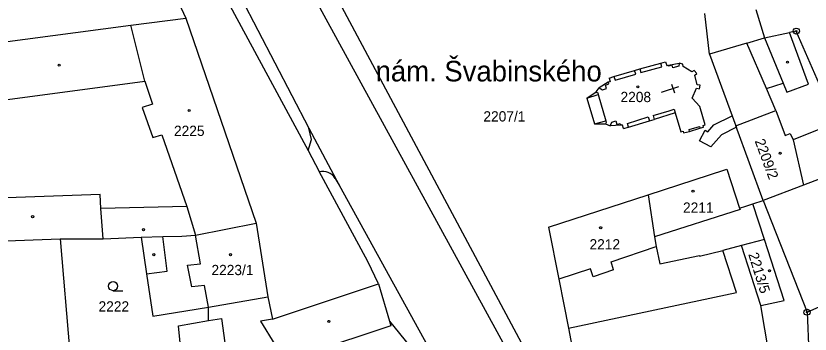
# Model space of a CAD drawing. Extents: x -755819 to -753140, y -1169796 to -1166000.
# Drawn here: x -754828 to -754696.6, y -1168215.6 to -1168163 of the extents above; entities that cross this region are included whole.
import ezdxf

# ---------------------------------------------------------------- set-up
doc = ezdxf.new("R2010")
doc.units = 0
for name, color, linetype in [('Vrstva 1', 7, 'Continuous'), ('Vrstva 15', 7, 'Continuous'), ('Vrstva 18', 7, 'Continuous'), ('Vrstva 19', 7, 'Continuous'), ('Vrstva 24', 7, 'Continuous'), ('Vrstva 25', 7, 'Continuous'), ('Vrstva 27', 7, 'Continuous'), ('Vrstva 4', 7, 'Continuous')]:
    doc.layers.add(name, color=color, linetype=linetype)

msp = doc.modelspace()

# ---------------------------------------------------------------- linework, layer by layer
at = {"layer": 'Vrstva 1'}
for p, q in [((-754811.6, -1168137.91), (-754799.93, -1168163.35)), ((-754801.63, -1168138.99), (-754779.58, -1168181.56)), ((-754787.61, -1168143.57), (-754722.5, -1168262.7)), ((-754801.06, -1168145.63), (-754779.7, -1168185.27)), ((-754731.38, -1168241.34), (-754774.47, -1168160.79)), ((-754713.27, -1168169.33), (-754714.08, -1168162.61)), ((-754809.01, -1168164.54), (-754799.93, -1168163.35)), ((-754799.93, -1168163.35), (-754788.28, -1168197.26)), ((-754834.8, -1168167.91), (-754809.01, -1168164.54)), ((-754698.93, -1168165.5), (-754700.07, -1168165.74)), ((-754692.48, -1168180.38), (-754698.93, -1168165.5)), ((-754707.1, -1168167.47), (-754704.17, -1168166.59)), ((-754704.17, -1168166.59), (-754700.07, -1168165.74)), ((-754707.1, -1168167.47), (-754713.27, -1168169.33)), ((-754713.27, -1168169.33), (-754708.92, -1168181.18)), ((-754724.84, -1168171.76), (-754721.32, -1168170.79)), ((-754721.32, -1168170.79), (-754720.55, -1168170.57)), ((-754720.55, -1168170.57), (-754720.37, -1168171.17)), ((-754720.07, -1168171.14), (-754718.28, -1168170.82)), ((-754717.69, -1168170.97), (-754718.28, -1168170.82)), ((-754717.67, -1168171.33), (-754717.69, -1168170.97)), ((-754729.09, -1168173.02), (-754725.68, -1168172.03)), ((-754725.68, -1168172.03), (-754724.84, -1168171.76)), ((-754720.37, -1168171.17), (-754720.07, -1168171.14)), ((-754716.23, -1168172.26), (-754717.67, -1168171.33)), ((-754715.85, -1168172.03), (-754716.23, -1168172.26)), ((-754715.39, -1168172.49), (-754715.85, -1168172.03)), ((-754729.91, -1168173.28), (-754729.09, -1168173.02)), ((-754729.91, -1168173.28), (-754729.72, -1168173.88)), ((-754715.72, -1168172.81), (-754715.39, -1168172.49)), ((-754715.32, -1168174.36), (-754715.72, -1168172.81)), ((-754732.01, -1168175.56), (-754731.55, -1168174.86)), ((-754730.03, -1168173.95), (-754731.55, -1168174.86)), ((-754729.72, -1168173.88), (-754730.03, -1168173.95)), ((-754714.83, -1168174.43), (-754715.32, -1168174.36)), ((-754714.92, -1168175.04), (-754714.83, -1168174.43)), ((-754733.56, -1168176.6), (-754732.01, -1168175.56)), ((-754716.14, -1168176.6), (-754715.44, -1168174.94)), ((-754715.44, -1168174.94), (-754714.92, -1168175.04)), ((-754733.56, -1168176.6), (-754732.32, -1168180.81)), ((-754714.9, -1168177.95), (-754716.14, -1168176.6)), ((-754714.02, -1168180.99), (-754714.9, -1168177.95)), ((-754723.21, -1168180.33), (-754722.43, -1168180.09)), ((-754718.95, -1168179.03), (-754722.43, -1168180.09)), ((-754718.95, -1168179.03), (-754718.01, -1168182.17)), ((-754732.32, -1168180.81), (-754730.48, -1168180.83)), ((-754730.48, -1168180.83), (-754729.71, -1168181.16)), ((-754727.93, -1168181.07), (-754729.71, -1168181.16)), ((-754727.68, -1168181.03), (-754727.93, -1168181.07)), ((-754727.49, -1168181.63), (-754727.68, -1168181.03)), ((-754727.49, -1168181.63), (-754726.67, -1168181.37)), ((-754726.67, -1168181.37), (-754723.21, -1168180.33)), ((-754714.87, -1168181.55), (-754714.27, -1168181.39)), ((-754714.36, -1168181.09), (-754714.02, -1168180.99)), ((-754714.27, -1168181.39), (-754714.36, -1168181.09)), ((-754704.43, -1168193.52), (-754708.92, -1168181.18)), ((-754779.58, -1168181.56), (-754774.52, -1168190.96)), ((-754718.01, -1168182.17), (-754717.66, -1168182.07)), ((-754717.66, -1168182.07), (-754717.58, -1168182.35)), ((-754717.58, -1168182.35), (-754716.59, -1168182.09)), ((-754716.59, -1168182.09), (-754714.87, -1168181.55)), ((-754779.7, -1168185.27), (-754777.83, -1168188.74)), ((-754689.23, -1168187.76), (-754697.74, -1168190.98)), ((-754769.81, -1168203.62), (-754777.83, -1168188.74)), ((-754723.43, -1168192.56), (-754710.76, -1168188.43)), ((-754710.76, -1168188.43), (-754710.42, -1168188.31)), ((-754710.42, -1168188.31), (-754708.31, -1168194.78)), ((-754774.52, -1168190.96), (-754758.33, -1168220.35)), ((-754697.74, -1168190.98), (-754704.43, -1168193.52)), ((-754739.9, -1168197.93), (-754723.43, -1168192.56)), ((-754723.43, -1168192.56), (-754722.37, -1168199.51)), ((-754708.31, -1168194.78), (-754707.26, -1168194.44)), ((-754707.26, -1168194.44), (-754706.12, -1168194.07)), ((-754706.12, -1168194.07), (-754704.43, -1168193.52)), ((-754704.21, -1168199.98), (-754706.12, -1168194.07)), ((-754704.43, -1168193.52), (-754697.16, -1168211.99)), ((-754798.33, -1168199.25), (-754788.28, -1168197.26)), ((-754788.28, -1168197.26), (-754786.32, -1168209.44)), ((-754739.9, -1168197.93), (-754738.21, -1168206.52)), ((-754838.3, -1168200.51), (-754820.71, -1168199.86)), ((-754820.71, -1168199.86), (-754813.6, -1168199.83)), ((-754820.71, -1168199.86), (-754819.05, -1168219.43)), ((-754813.6, -1168199.83), (-754807.3, -1168199.58)), ((-754807.3, -1168199.58), (-754803.73, -1168199.45)), ((-754807.3, -1168199.58), (-754806.4, -1168205.63)), ((-754803.73, -1168199.45), (-754800.55, -1168199.44)), ((-754800.55, -1168199.44), (-754798.33, -1168199.25)), ((-754722.37, -1168199.51), (-754722.13, -1168201.15)), ((-754722.13, -1168201.15), (-754721.53, -1168203.98)), ((-754707.98, -1168200.95), (-754711.11, -1168201.76)), ((-754704.21, -1168199.98), (-754707.98, -1168200.95)), ((-754704.81, -1168210.9), (-754707.98, -1168200.95)), ((-754700.95, -1168210.05), (-754704.21, -1168199.98)), ((-754714.94, -1168202.73), (-754711.11, -1168201.76)), ((-754708.82, -1168208.73), (-754711.11, -1168201.76)), ((-754768.03, -1168207.29), (-754769.81, -1168203.62)), ((-754721.53, -1168203.98), (-754714.97, -1168202.6)), ((-754714.97, -1168202.6), (-754714.94, -1168202.73)), ((-754697.16, -1168211.99), (-754681.79, -1168205.05)), ((-754806.4, -1168205.63), (-754805.36, -1168212.65)), ((-754785.59, -1168213.12), (-754768.03, -1168207.29)), ((-754768.03, -1168207.29), (-754766.23, -1168213.46)), ((-754738.21, -1168206.52), (-754737.39, -1168210.73)), ((-754736.62, -1168214.63), (-754708.82, -1168208.73)), ((-754786.32, -1168209.44), (-754785.59, -1168213.12)), ((-754704.81, -1168210.9), (-754700.95, -1168210.05)), ((-754805.36, -1168212.65), (-754796.14, -1168211.15)), ((-754796.14, -1168213.38), (-754796.14, -1168211.15)), ((-754737.39, -1168210.73), (-754736.62, -1168214.63)), ((-754702.06, -1168227.01), (-754704.81, -1168210.9)), ((-754796.14, -1168213.38), (-754794.03, -1168213.02)), ((-754794.03, -1168213.02), (-754793.32, -1168218.26)), ((-754697.16, -1168211.99), (-754695.32, -1168251.73)), ((-754801.13, -1168214.22), (-754796.14, -1168213.38)), ((-754800.63, -1168219.35), (-754801.13, -1168214.22)), ((-754785.59, -1168213.12), (-754787.55, -1168213.45)), ((-754787.55, -1168213.45), (-754785.2, -1168217.35)), ((-754766.23, -1168213.46), (-754760.42, -1168220.58)), ((-754736.62, -1168214.63), (-754734.07, -1168227.62))]:
    msp.add_line(p, q, dxfattribs=at)
at = {"layer": 'Vrstva 24'}
for centre, radius in [((-754698.93, -1168165.5), 0.5), ((-754698.93, -1168165.5), 0.1), ((-754697.16, -1168211.99), 0.5), ((-754697.16, -1168211.99), 0.1)]:
    msp.add_circle(centre, radius, dxfattribs=at)
at = {"layer": 'Vrstva 25'}
for p, q in [((-754721.22, -1168175.6), (-754718.37, -1168174.67)), ((-754719.55, -1168174.27), (-754719.09, -1168175.69)), ((-754811.94, -1168208.43), (-754810.34, -1168208.43))]:
    msp.add_line(p, q, dxfattribs=at)
for centre, radius in [((-754820.85, -1168171.13), 0.175), ((-754700.39, -1168170.63), 0.175), ((-754725.14, -1168174.72), 0.175), ((-754799.35, -1168178.62), 0.175), ((-754701.6, -1168185.7), 0.175), ((-754716.01, -1168191.96), 0.175), ((-754825.25, -1168196.18), 0.175), ((-754806.91, -1168198.34), 0.175), ((-754731.29, -1168198.02), 0.175), ((-754805.19, -1168202.48), 0.175), ((-754792.51, -1168202.48), 0.175), ((-754703.37, -1168205.13), 0.175), ((-754811.94, -1168207.68), 0.75), ((-754776.25, -1168213.51), 0.175)]:
    msp.add_circle(centre, radius, dxfattribs=at)
at = {"layer": 'Vrstva 27'}
for p, q in [((-754712.59, -1168181.02), (-754709.53, -1168179.53)), ((-754709.53, -1168179.53), (-754708.92, -1168181.18)), ((-754713.54, -1168182.14), (-754712.59, -1168181.02)), ((-754708.84, -1168181.41), (-754711.33, -1168182.64)), ((-754708.92, -1168181.18), (-754708.84, -1168181.41)), ((-754714.95, -1168183.65), (-754714.01, -1168181.89)), ((-754714.01, -1168181.89), (-754713.54, -1168182.14)), ((-754711.33, -1168182.64), (-754713.06, -1168184.66)), ((-754713.06, -1168184.66), (-754714.95, -1168183.65))]:
    msp.add_line(p, q, dxfattribs=at)
at = {"layer": 'Vrstva 4'}
for p, q in [((-754705.65, -1168161.91), (-754704.17, -1168166.59)), ((-754806.7, -1168173.78), (-754809.01, -1168164.54)), ((-754704.17, -1168166.59), (-754701.11, -1168174.1)), ((-754696.93, -1168174.3), (-754700.07, -1168165.74)), ((-754703.87, -1168174.97), (-754707.1, -1168167.47)), ((-754721.18, -1168171.4), (-754721.32, -1168170.79)), ((-754718.28, -1168170.82), (-754718.39, -1168171.27)), ((-754725.49, -1168172.63), (-754725.68, -1168172.03)), ((-754724.84, -1168171.76), (-754724.67, -1168172.35)), ((-754724.67, -1168172.35), (-754721.18, -1168171.4)), ((-754720.05, -1168171.29), (-754720.07, -1168171.14)), ((-754719.46, -1168171.13), (-754720.05, -1168171.29)), ((-754719.33, -1168171.56), (-754719.46, -1168171.13)), ((-754718.39, -1168171.27), (-754719.33, -1168171.56)), ((-754729.09, -1168173.02), (-754728.9, -1168173.62)), ((-754728.9, -1168173.62), (-754725.49, -1168172.63)), ((-754833.4, -1168177.36), (-754806.7, -1168173.78)), ((-754806.7, -1168173.78), (-754805.42, -1168177.58)), ((-754731.55, -1168174.86), (-754731.01, -1168175.22)), ((-754730.51, -1168174.42), (-754729.93, -1168174.24)), ((-754730.33, -1168175.01), (-754730.51, -1168174.42)), ((-754729.93, -1168174.24), (-754730.03, -1168173.95)), ((-754703.87, -1168174.97), (-754701.11, -1168174.1)), ((-754701.11, -1168174.1), (-754700.5, -1168175.58)), ((-754700.5, -1168175.58), (-754696.93, -1168174.3)), ((-754733.56, -1168176.6), (-754731.7, -1168175.96)), ((-754732.01, -1168175.56), (-754731.78, -1168175.7)), ((-754731.78, -1168175.7), (-754731.7, -1168175.96)), ((-754731.7, -1168175.96), (-754730.44, -1168180.33)), ((-754731.01, -1168175.22), (-754730.33, -1168175.01)), ((-754702.3, -1168178.62), (-754703.87, -1168174.97)), ((-754805.42, -1168177.58), (-754807.13, -1168178.13)), ((-754807.13, -1168178.13), (-754805.38, -1168183.1)), ((-754722.61, -1168179.47), (-754719.94, -1168178.66)), ((-754719.94, -1168178.66), (-754719.14, -1168178.42)), ((-754719.14, -1168178.42), (-754718.95, -1168179.03)), ((-754708.92, -1168181.18), (-754702.3, -1168178.62)), ((-754702.3, -1168178.62), (-754700.76, -1168182.76)), ((-754726.88, -1168180.78), (-754723.45, -1168179.69)), ((-754723.45, -1168179.69), (-754723.21, -1168180.33)), ((-754722.61, -1168179.47), (-754722.43, -1168180.09)), ((-754732.32, -1168180.81), (-754730.44, -1168180.33)), ((-754730.36, -1168180.59), (-754730.48, -1168180.83)), ((-754730.44, -1168180.33), (-754730.36, -1168180.59)), ((-754729.71, -1168181.16), (-754729.44, -1168180.56)), ((-754729.44, -1168180.56), (-754728.81, -1168180.36)), ((-754728.81, -1168180.36), (-754728.62, -1168180.96)), ((-754728.62, -1168180.96), (-754728.05, -1168180.78)), ((-754728.05, -1168180.78), (-754727.93, -1168181.07)), ((-754726.67, -1168181.37), (-754726.88, -1168180.78)), ((-754716.68, -1168181.78), (-754714.95, -1168181.27)), ((-754714.95, -1168181.27), (-754714.87, -1168181.55)), ((-754692.4, -1168180.64), (-754699.47, -1168183.49)), ((-754805.38, -1168183.1), (-754803.87, -1168182.68)), ((-754803.87, -1168182.68), (-754799.75, -1168194.48)), ((-754779.1, -1168183.4), (-754779.58, -1168181.56)), ((-754716.59, -1168182.09), (-754716.68, -1168181.78)), ((-754700.76, -1168182.76), (-754699.92, -1168182.43)), ((-754699.92, -1168182.43), (-754699.47, -1168183.49)), ((-754779.7, -1168185.27), (-754779.1, -1168183.4)), ((-754699.47, -1168183.49), (-754697.74, -1168190.98)), ((-754775.23, -1168189.86), (-754774.52, -1168190.96)), ((-754814.07, -1168192.5), (-754838.83, -1168193.42)), ((-754813.98, -1168194.81), (-754814.07, -1168192.5)), ((-754799.75, -1168194.48), (-754813.98, -1168194.81)), ((-754799.75, -1168194.48), (-754798.33, -1168199.25)), ((-754813.6, -1168199.83), (-754813.98, -1168194.81)), ((-754708.24, -1168194.98), (-754722.37, -1168199.51)), ((-754708.31, -1168194.78), (-754708.24, -1168194.98)), ((-754802.99, -1168205.2), (-754803.73, -1168199.45)), ((-754797.46, -1168203.97), (-754798.33, -1168199.25)), ((-754729.57, -1168203.66), (-754722.13, -1168201.15)), ((-754729.17, -1168204.99), (-754729.57, -1168203.66)), ((-754799.63, -1168204.22), (-754797.46, -1168203.97)), ((-754798.94, -1168207.81), (-754799.63, -1168204.22)), ((-754732.99, -1168204.81), (-754738.21, -1168206.52)), ((-754732.54, -1168206.14), (-754732.99, -1168204.81)), ((-754729.17, -1168204.99), (-754732.54, -1168206.14)), ((-754806.4, -1168205.63), (-754802.99, -1168205.2)), ((-754796.8, -1168207.56), (-754798.94, -1168207.81)), ((-754796.14, -1168211.15), (-754796.8, -1168207.56)), ((-754796.14, -1168211.15), (-754786.32, -1168209.44)), ((-754766.01, -1168214.22), (-754783.18, -1168219.92)), ((-754766.23, -1168213.46), (-754766.01, -1168214.22))]:
    msp.add_line(p, q, dxfattribs=at)
msp.add_arc((-754777.31, -1168191.12), 2.43, 31.1015, 102.2887, dxfattribs=at)

# ---------------------------------------------------------------- texts
at = {"layer": 'Vrstva 15'}
msp.add_text('nám. Švabinského', height=3.4, dxfattribs=at).set_placement((-754768.52, -1168173.82))
at = {"layer": 'Vrstva 18'}
for s, p in [('2207/1', (-754750.69, -1168180.45)), ('2222', (-754814.35, -1168211.88))]:
    msp.add_text(s, height=1.7, dxfattribs=at).set_placement(p)
at = {"layer": 'Vrstva 19'}
for s, p in [('2208', (-754728.01, -1168177.24)), ('2225', (-754801.87, -1168182.84)), ('2211', (-754717.67, -1168195.54)), ('2212', (-754733.14, -1168201.61)), ('2223/1', (-754795.67, -1168205.86))]:
    msp.add_text(s, height=1.7, dxfattribs=at).set_placement(p)
for s, rotation, p in [('2209/2', 290.4323, (-754705.84, -1168183.67)), ('2213/5', 287.2237, (-754706.9, -1168202.4))]:
    msp.add_text(s, height=1.7, rotation=rotation, dxfattribs=at).set_placement(p)

doc.saveas('drawing.dxf')
